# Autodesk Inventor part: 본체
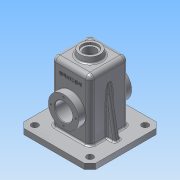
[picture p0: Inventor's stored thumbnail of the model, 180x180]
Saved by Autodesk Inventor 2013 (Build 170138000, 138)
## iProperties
Created: 2016-02
Part Number: 본체
Material: 알루미늄 6061
Document SubType Name: Modeling
Designer: Administrator
Density: 2.71 g/cm^3
Mass: 932.761 g
Surface Area: 1044.48 cm^2
Volume: 344.192 cm^3
Author: Administrator
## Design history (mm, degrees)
sketch "스케치1"
  geometry: L1 (-35, 35)-(35, 35); L2 (35, 35)-(35, -35); L3 (35, -35)-(-35, -35); L4 (-35, -35)-(-35, 35); L5 (-35, 35)-(35, -35); L6 (35, 35)-(-35, -35); 1 further point
  constraints: 12 end point, 2 midpoint, 2 parallel, 1 horizontal, 1 perpendicular
  dimensions: "d0" = 70 distance of L2.end L3.end; "d1" = 70 distance of L1.end L2.end
extrude "돌출1" new body sketch "스케치1" distance "d2" = 110; taper "d3" = 0 deg
feature "쉘1" dims "d4" = 5
fillet "모깎기1" dims "d5" = 8
fillet "모깎기2" dims "d6" = 8
sketch "스케치2"
  geometry: L1 (-30, 30)-(30, 30) reference; L2 (30, 30)-(30, -30) reference; L3 (30, -30)-(-30, -30) reference; L4 (-30, -30)-(-30, 30) reference; L5 (-65, 65)-(65, 65); L6 (65, 65)-(65, -65); L7 (65, -65)-(-65, -65); L8 (-65, -65)-(-65, 65); L9 (-65, 65)-(65, -65); L10 (65, 65)-(-65, -65); 1 further point
  constraints: 12 end point, 2 midpoint, 2 parallel, 1 horizontal, 1 perpendicular
  dimensions: "d7" = 130 distance of L6.end L7.end; "d8" = 130 distance of L5.end L6.end
extrude "돌출2" join sketch "스케치2" distance "d9" = 10; taper "d10" = 0 deg
fillet "모깎기3" dims "d11" = 3
fillet "모깎기4" dims "d12" = 3
sketch "스케치4"
  geometry: L1 (-50, 0)-(-35, 85.069); L2 (35, 102)-(35, 0) reference; L3 (35, 0)-(65, 0) reference; L4 (65, 0)-(65, -10) reference; L5 (65, -10)-(30, -10) reference; L6 (30, -10)-(30, 102) reference; L7 (27, 105)-(-27, 105) reference; L8 (-30, 102)-(-30, -10) reference; L9 (-30, -10)-(-65, -10) reference; L10 (-65, -10)-(-65, 0) reference; L11 (-65, 0)-(-35, 0) reference; L12 (-35, 0)-(-35, 102) reference; L13 (-27, 110)-(27, 110) reference; A1 r 8 centre (27, 102) between (35, 102) and (27, 110) reference; A2 r 3 centre (27, 102) between (30, 102) and (27, 105) reference; A3 r 3 centre (-27, 102) between (-27, 105) and (-30, 102) reference; A4 r 8 centre (-27, 102) between (-27, 110) and (-35, 102) reference; 1 further point
  constraints: 2 end point, 1 midpoint, 1 point on line
  dimensions: "d13" = 10 deg angle of L1 L10; "d14" = 15 distance from line of L1.start L10
feature "리브1" sketch "스케치4" dims "d15" = 10, "d16" = 10, "d17" = 0, "d18" = 0, "d19" = 1, "d20" = 1
sketch "스케치5"
  geometry: L1 (54, 0)-(0, 0) reference; L2 (0, 102)-(0, 0) reference; L3 (0, 102)-(-38, 102) reference; L4 (-38, 102)-(-38, 112) reference; L5 (-38, 112)-(92, 112) reference; L6 (92, 112)-(92, 102) reference; L7 (92, 102)-(54, 102) reference; L8 (54, 102)-(0, 102) reference; L9 (54, 102)-(54, 0) reference; L10 (54, 0)-(0, 0) reference; L11 (0, 102)-(0, 0) reference; L12 (0, 102)-(-38, 102) reference; L13 (-38, 102)-(-38, 112) reference; L14 (-38, 112)-(92, 112) reference; L15 (92, 112)-(92, 102) reference; L16 (92, 102)-(54, 102) reference; L17 (54, 102)-(0, 102) reference; L18 (54, 102)-(54, 0) reference; L19 (92, 102)-(-38, 102) reference; C1 r 27.5 at (27, 57); 2 further points
  constraints: 1 centre point, 1 midpoint, 1 vertical alignment
  dimensions: "d21" = 55 diameter of C1; "d22" = 55 distance from line of L14 C1.centre
extrude "돌출3" join sketch "스케치5" distance "d23" = 13; taper "d24" = 0 deg
sketch "스케치6"
  geometry: L1 (0, 119.416)-(54, 119.416) reference; L2 (61.416, 112)-(61.416, 10) reference; L3 (61.416, 10)-(92, 10) reference; L4 (92, 10)-(92, 0) reference; L5 (92, 0)-(54, 0) reference; L6 (54, 0)-(0, 0) reference; L7 (0, 0)-(-38, 0) reference; L8 (-38, 0)-(-38, 10) reference; L9 (-38, 10)-(-7.416, 10) reference; L10 (-7.416, 10)-(-7.416, 112) reference; L11 (54, 112)-(54, 0) reference; L12 (0, 112)-(54, 112) reference; L13 (0, 0)-(0, 112) reference; L14 (0, 119.416)-(54, 119.416) reference; L15 (61.416, 112)-(61.416, 10) reference; L16 (61.416, 10)-(92, 10) reference; L17 (92, 10)-(92, 0) reference; L18 (92, 0)-(54, 0) reference; L19 (54, 0)-(0, 0) reference; L20 (0, 0)-(-38, 0) reference; L21 (-38, 0)-(-38, 10) reference; L22 (-38, 10)-(-7.416, 10) reference; L23 (-7.416, 10)-(-7.416, 112) reference; L24 (54, 112)-(54, 0) reference; L25 (0, 112)-(54, 112) reference; L26 (0, 0)-(0, 112) reference; C1 r 27.5 at (27, 55) reference; A1 r 7.416 centre (54, 112) between (61.416, 112) and (54, 119.416) reference; A2 r 7.416 centre (0, 112) between (0, 119.416) and (-7.416, 112) reference; A3 r 7.416 centre (54, 112) between (61.416, 112) and (54, 119.416) reference; A4 r 7.416 centre (0, 112) between (0, 119.416) and (-7.416, 112) reference; 1 further point
extrude "돌출4" join sketch "스케치6" distance "d25" = 7; taper "d26" = -45 deg
sketch "스케치8"
  geometry: C1 r 27.5 at (0, 0) reference; C2 r 16 at (0, 0); 1 further point
  constraints: 1 centre point, 1 coincident
  dimensions: "d27" = 32 diameter of C2
extrude "돌출5" cut sketch "스케치8" stored distance "d28" = 7; taper "d29" = 0 deg
chamfer "모따기1" distance "d30" = 1; stored, may be unused: second distance "d31" = 2, angle "d32" = 45 deg
fillet "모깎기5" dims "d33" = 0.5
fillet "모깎기6" dims "d34" = 0.5
sketch "스케치9"
  geometry: C1 r 20 at (0, 0); 1 further point
  constraints: 1 centre point, 1 coincident
  dimensions: "d35" = 40 diameter of C1
extrude "돌출6" join sketch "스케치9" distance "d36" = 10; taper "d37" = -10 deg
hole "구멍1" diameter "d40" = 21; stored, may be unused: countersink angle "d44" = 90 deg, drill point angle "d46" = 0 deg; dims "d38" = 10, "d39" = 10, "d41" = 6, "d42" = 28, "d43" = 4, "d45" = 8
sketch "스케치12"
  geometry: C1 r 27.5 at (0, 0) reference; 2 further points
  constraints: 1 vertical alignment
  dimensions: "d47" = 22.5 distance of C1.centre point (0, -22.5)
hole "구멍2" sketch "스케치12" at (0, -22.5) diameter "d48" = 3.242; stored, may be unused: countersink angle "d52" = 90 deg, drill point angle "d54" = 118 deg; dims "d49" = 8, "d50" = 28, "d51" = 4, "d53" = 10
fillet "모깎기7" dims "d58" = 3
fillet "모깎기8" dims "d59" = 3
fillet "모깎기9" dims "d60" = 3
fillet "모깎기10" dims "d61" = 3
sketch "스케치14"
  geometry: L1 (65, -65)-(65, 65) reference; L2 (65, 65)-(-65, 65) reference; L3 (-65, 65)-(-65, -65) reference; C1 r 6 at (-50, 50); C2 r 6 at (50, 50); 1 further point
  constraints: 2 centre point, 1 horizontal alignment
  dimensions: "d62" = 12 diameter of C1; "d63" = 12 diameter of C2; "d64" = 15 distance from line of L3 C1.centre; "d65" = 15 distance from line of L2 C1.centre; "d66" = 15 distance from line of L1 C2.centre
extrude "돌출7" cut sketch "스케치14" stored distance "d67" = 10; taper "d68" = 0 deg
chamfer "모따기2" distance "d69" = 10; stored, may be unused: second distance "d70" = 2, angle "d71" = 45 deg
sketch "스케치15"
  geometry: L1 (8.763, 18)-(45.237, 18) reference; L2 (62, -99)-(62, 0) reference; 2 further points
  constraints: 1 other
  dimensions: "d72" = 30 distance from line of L1 point (27, -12); "d73" = 35 distance from line of L2 point (27, -12)
feature "엠보싱1" sketch "스케치15" dims "d74" = 0.5, "d75" = 0
fillet "모깎기11" dims "d76" = 0.5
fillet "모깎기12" dims "d77" = 0.5
node "솔리드1"
mirror "대칭1"
mirror "대칭2"
pattern_circular "원형 패턴1" dims angle "d56" = 360 deg
mirror "대칭3"
mirror "대칭4"
node "투영된 루프1"
node "절단 모서리 투영1"
node "절단 모서리 투영2"
node "절단 모서리 투영3"
node "절단 모서리 투영4"
node "절단 모서리 투영5"
